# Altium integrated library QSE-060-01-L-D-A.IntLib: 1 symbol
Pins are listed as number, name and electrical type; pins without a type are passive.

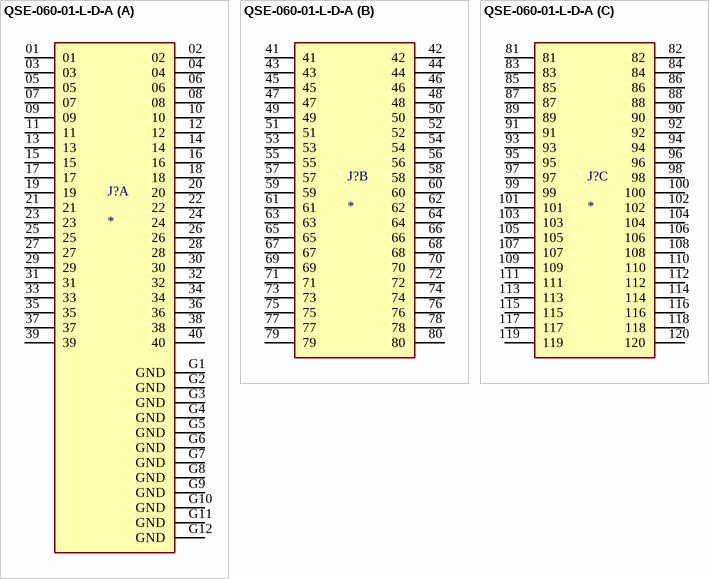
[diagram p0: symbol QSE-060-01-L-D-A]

## QSE-060-01-L-D-A
designator J?
120 Position Connector Receptacle, Center Strip Contacts Surface Mount Gold; MF: Samtec Inc.; MP: QSE-060-01-L-D-A
footprint SAMTEC_QSE-060-01-L-D-A
part A pins: 01, 02, 03, 04, 05, 06, 07, 08, 09, 10, 11, 12, 13, 14, 15, 16, 17, 18, 19, 20, 21, 22, 23, 24, 25, 26, 27, 28, 29, 30, 31, 32, 33, 34, 35, 36, 37, 38, 39, 40, G1 GND (power), G2 GND (power), G3 GND (power), G4 GND (power), G5 GND (power), G6 GND (power), G7 GND (power), G8 GND (power), G9 GND (power), G10 GND (power), G11 GND (power), G12 GND (power)
part B pins: 41, 42, 43, 44, 45, 46, 47, 48, 49, 50, 51, 52, 53, 54, 55, 56, 57, 58, 59, 60, 61, 62, 63, 64, 65, 66, 67, 68, 69, 70, 71, 72, 73, 74, 75, 76, 77, 78, 79, 80
part C pins: 81, 82, 83, 84, 85, 86, 87, 88, 89, 90, 91, 92, 93, 94, 95, 96, 97, 98, 99, 100, 101, 102, 103, 104, 105, 106, 107, 108, 109, 110, 111, 112, 113, 114, 115, 116, 117, 118, 119, 120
